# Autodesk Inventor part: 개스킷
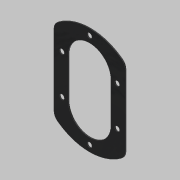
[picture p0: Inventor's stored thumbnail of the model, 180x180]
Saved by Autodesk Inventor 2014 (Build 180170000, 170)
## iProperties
Created: 2019-03
Part Number: 개스킷
Material: 고무
Document SubType Name: Modeling
Designer: mduedu
Density: 1 g/cm^3
Appearance: 고무 - 검은색 - 버전 1.1
Author: mduedu
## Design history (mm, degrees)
sketch "스케치1"
  geometry: L1 (-44.721, -40)-(44.721, -40); L2 (44.721, 40)-(-44.721, 40); A1 r 60 centre (0, 0) between (44.721, -40) and (44.721, 40); A2 r 60 centre (0, 0) between (-44.721, 40) and (-44.721, -40); 5 further points
  constraints: 6 point on circle, 4 end point, 2 centre point, 2 coincident, 2 horizontal alignment, 2 midpoint, 2 vertical alignment, 1 horizontal, 1 parallel
  dimensions: "d0" = 60 radius of A1; "d2" = 80 distance between parallel lines of L2 L1
extrude "돌출1" new body sketch "스케치1" distance "d3" = 1; taper "d4" = 0 deg
fillet "모깎기1" dims "d5" = 10
sketch "스케치2" dims "d6" = 48
  geometry: L1 (-24, -22)-(24, -22); L2 (24, -22)-(24, 22); L3 (24, 22)-(-24, 22); L4 (-24, 22)-(-24, -22); L5 (-24, -22)-(24, 22); L6 (24, -22)-(-24, 22); 3 further points
  constraints: 12 end point, 4 midpoint, 2 horizontal alignment, 2 parallel, 1 horizontal, 1 perpendicular, 4 other
  dimensions: "d8" = 22 distance from line of L3 point (0, 0)
extrude "돌출2" cut sketch "스케치2" stored distance "d9" = 1; taper "d10" = 0 deg
sketch "스케치3" dims "d0" = 60, "d2" = 80
  geometry: L1 (31, -22)-(31, 22); L2 (-31, 22)-(-31, -22); L3 (-31, -22)-(31, 22); L4 (31, -22)-(-31, 22); A1 r 31 centre (0, 22) between (31, 22) and (-31, 22); A2 r 31 centre (0, -22) between (-31, -22) and (31, -22); 8 further points
  constraints: 8 end point, 6 point on circle, 4 coincident, 4 midpoint, 3 tangent, 2 centre point, 2 vertical alignment, 1 parallel
  dimensions: "d11" = 31 radius of A1; "d13" = 44 distance of A2.centre A1.centre
hole "구멍1" sketch "스케치3" at (-31, 22), (-31, -22), (31, -22), (31, 22), (0, -53), (0, 53) diameter "d14" = 5.5; stored, may be unused: countersink angle "d18" = 90 deg, drill point angle "d20" = 118 deg; dims "d15" = 6, "d16" = 4, "d17" = 2, "d19" = 8
node "솔리드1"
